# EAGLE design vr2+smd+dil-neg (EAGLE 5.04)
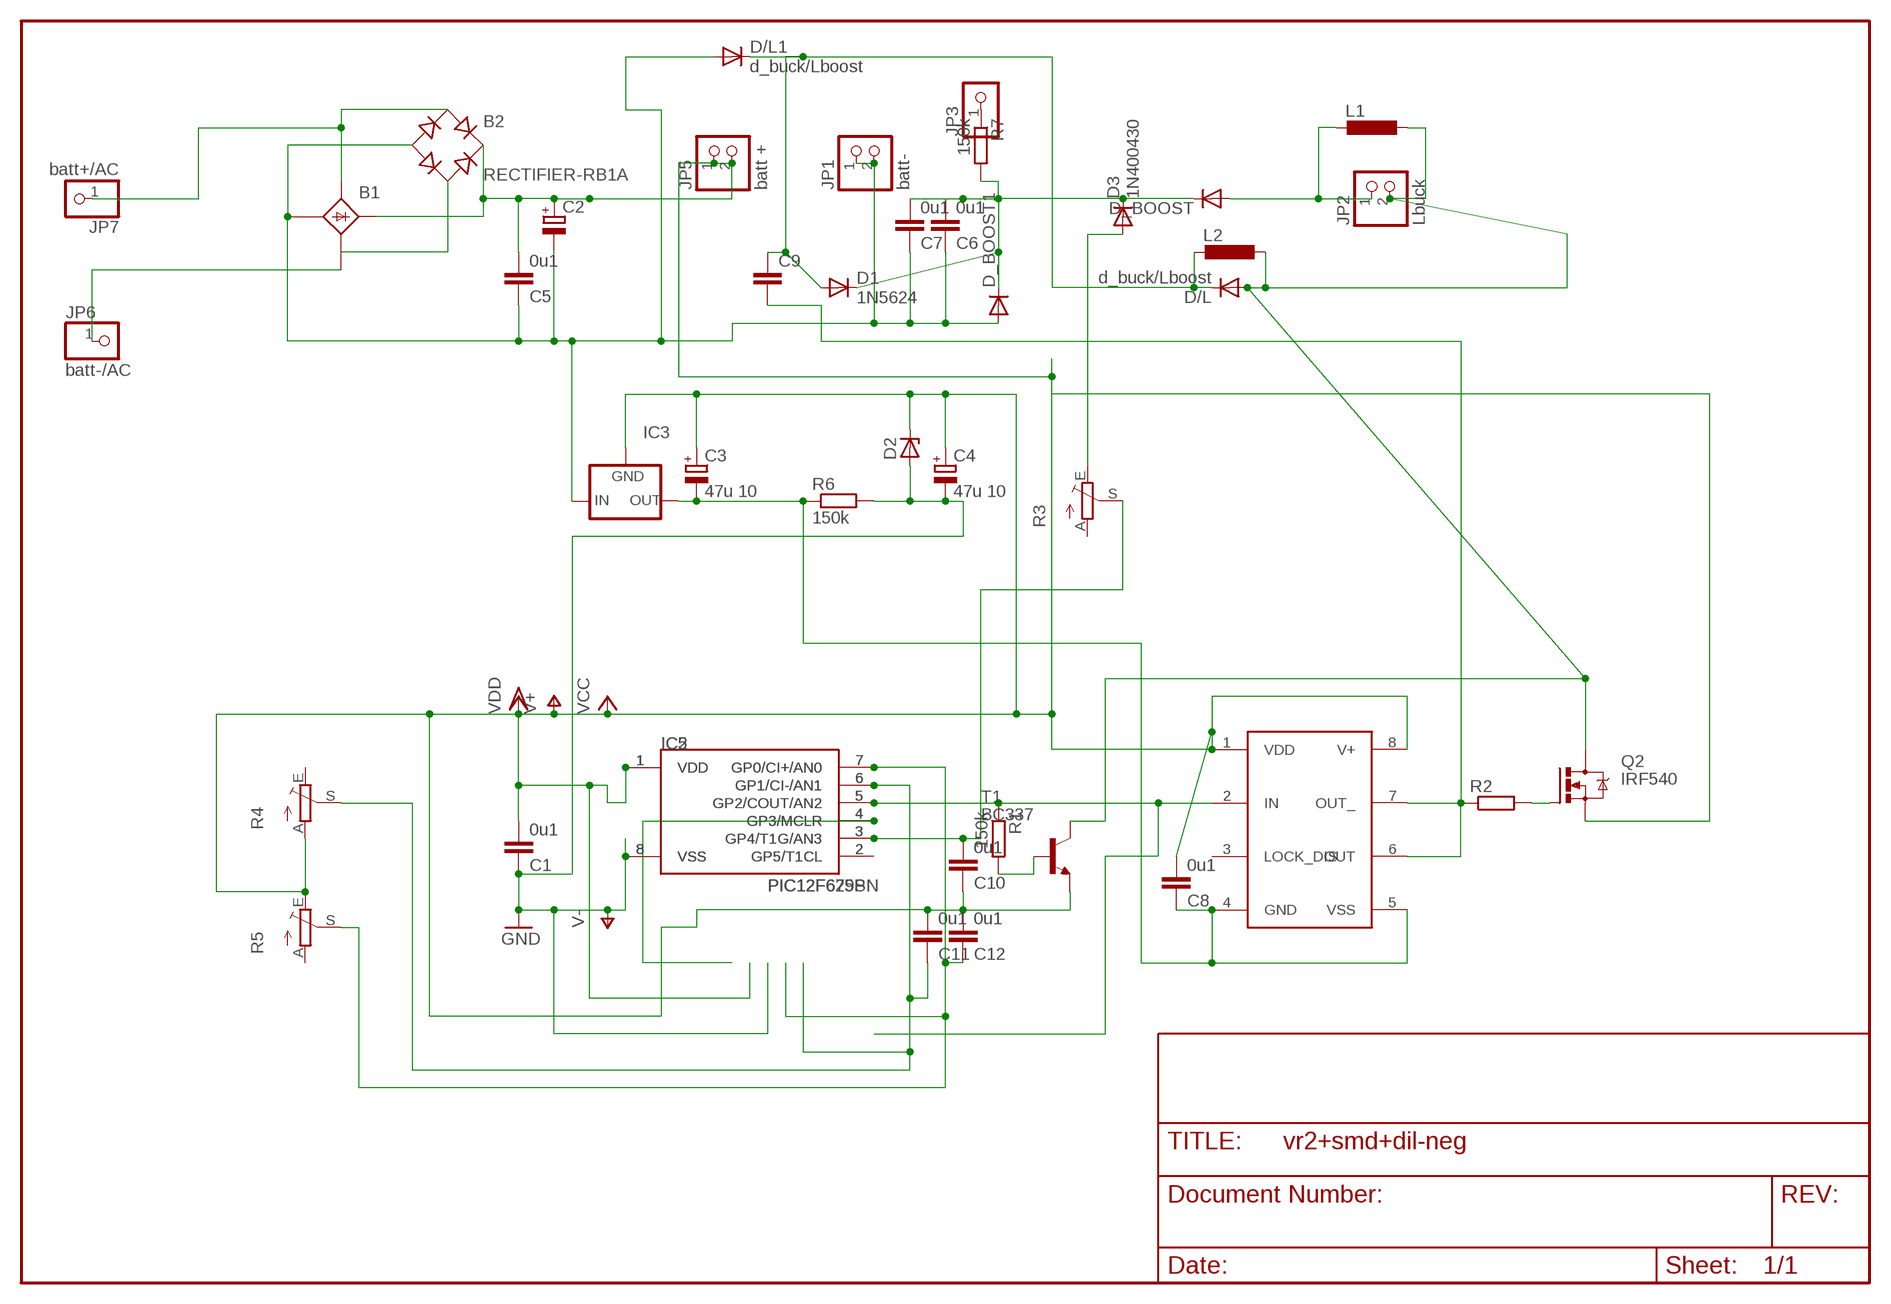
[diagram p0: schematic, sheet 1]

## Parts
B1  B25A-  [B25A-]
B2  RECTIFIER-RB1A  [RB1A]
C1  0u1  C-EUC1206  [C1206]
C2  CPOL-EUE7.5-18  [E7,5-18]
C3  47u 10  CPOL-EUE2,5-6E  [E2,5-6E]
C4  47u 10  CPOL-EUE2.5-6  [E2,5-6]
C5  0u1  C-EUC1206  [C1206]
C6  0u1  C-EUC1206  [C1206]
C7  0u1  C-EUC1206  [C1206]
C8  0u1  C-EUC1206  [C1206]
C9  C-EU050-024X044  [C050-024X044]
C10  0u1  C-EUC1206  [C1206]
C11  0u1  C-EUC1206  [C1206]
C12  0u1  C-EUC1206  [C1206]
D1  1N5624  [DO201-15]
D2  ZENER-DIODESMB  [SMB]
D3  1N400430  [DO41-30]
D/L  d_buck/Lboost  DIODE-C1702-05  [C1702-05]
D/L1  d_buck/Lboost  DIODE-DO201-15  [DO201-15]
D_BOOST  DIODE-DO201-15  [DO201-15]
D_BOOST1  DIODE-DO201-15  [DO201-15]
IC1  TC4432X  [SO-08]
IC2  PIC12F675SN  [SO-08]
IC3  79LXX  [79LXX]
IC5  PIC12F629P  [DIL8]
JP1  batt-  PINHD-1X2  [1X02]
JP2  Lbuck  PINHD-1X2  [1X02]
JP3  PINHD-1X1  [1X01]
JP5  batt +  PINHD-1X2  [1X02]
JP6  batt-/AC  PINHD-1X1  [1X01]
JP7  batt+/AC  PINHD-1X1  [1X01]
L1  DO3316P  [DO3316P]
L2  DO3316P  [DO3316P]
Q2  IRF540  [TO220BV]
R1  150k  R-EU_0617/17  [0617/17]
R2  R-EU_R1206  [R1206]
R3  TRIM_EU-CA6V  [CA6V]
R4  TRIM_EU-CA6V  [CA6V]
R5  TRIM_EU-CA6V  [CA6V]
R6  150k  R-EU_0204/7  [0204/7]
R7  150k  R-EU_0207/12  [0207/12]
T1  BC337  [TO92]

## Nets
LOAD: C6.2 C7.2 D1.C D3.C D_BOOST1.C D_BOOST.C R7.2
N$2: C9.1 D1.A D/L1.C D/L.C L2.1
N$3: B1.AC2-(AC2) JP6.1
N$5: D_BOOST.A JP2.1 L1.1
N$6: R1.2 T1.2(B)
N$7: C9.2 IC1.6(OUT) IC1.7(OUT_) R2.1
N$8: B1.AC1 B2.AC1 JP7.1
N$9: D/L.A JP2.2 L1.2 L2.2 Q2.D T1.3(C)
N$10: IC2.4(GP3/MCLR) IC5.4(GP3/MCLR)
N$11: B1.AC2 B2.AC2
N$12: C10.2 IC2.3(GP4/T1G/AN3) IC5.3(GP4/T1G/AN3) R3.S
N$13: C12.1 IC2.7(GP0/CI+/AN0) IC5.7(GP0/CI+/AN0) R5.S
N$14: IC1.2(IN) IC2.5(GP2/COUT/AN2) IC5.5(GP2/COUT/AN2) R1.1
N$15: C11.1 IC2.6(GP1/CI-/AN1) IC5.6(GP1/CI-/AN1) R4.S
N$16: D3.A R3.E
N$17: Q2.G R2.2
N$18: IC2.2(GP5/T1CL) IC5.2(GP5/T1CL)
N$19: JP3.1 R7.1
N$21: B1.-1(-) B2.- C2.- C5.1 C6.1 C7.1 D/L1.A D_BOOST1.A IC3.IN JP1.1 JP1.2
N$22: C3.- C8.1 IC1.4(GND) IC1.5(VSS) IC3.OUT R6.1
V+: B1.+ B2.+ C1.2 C2.+ C3.+ C4.+ C5.2 C8.2 C10.1 C11.2 C12.2 D2.C IC1.1(VDD) IC1.8(V+) IC2.1(VDD) IC3.GND IC5.1(VDD) JP5.1 JP5.2 Q2.S R4.A R5.E T1.1(E) ; supply symbol labelled VCC, VDD
V-: C1.1 C4.- D2.A IC2.8(VSS) IC5.8(VSS) R6.2 ; supply symbol labelled GND
Unconnected: B1.+1(+) B1.- B1.AC1-(AC1) IC1.3(LOCK_DIS) R3.A R4.E R5.A

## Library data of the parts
B1 = rectifier:B25A-: RECTIFIER 25-A bridge
B2 = rectifier:RECTIFIER-: Rectifier
C1 C5-C8 C10-C12 = rcl:C-EU: CAPACITOR, European symbol
C2-C4 = rcl:CPOL-EU: POLARIZED CAPACITOR, European symbol
C9 = rcl-2:C-EU: CAPACITOR, European symbol
D1 = diode-1:1N5624: DIODE
D2 = diode-1:ZENER-DIODE: Z-Diode
D3 = diode-1:1N4004: DIODE
D/L D/L1 D_BOOST D_BOOST1 = diode:DIODE-: DIODE
IC1 = microchip:TC4432
IC2 = microchip-3:PIC12F6*: uPC nW 1k Program Flash memory 2x Timer Comparator 10b A/D converter/ 4xIN
IC3 = v-reg:79LXX: VOLTAGE REGULATOR
IC5 = microchip-5:PIC12F6*: uPC nW 1k Program Flash memory 2x Timer Comparator 10b A/D converter/ 4xIN
JP1 JP2 JP5 = pinhead:PINHD-1X2: PIN HEADER
JP3 JP6 JP7 = pinhead:PINHD-1X1: PIN HEADER
L1 L2 = inductor-coilcraft:DO3316P: COILCRAFT
Q2 = transistor-power:IRF540: HEXFET Power MOSFET
R1 R6 R7 = rcl:R-EU_: RESISTOR, European symbol
R2 = rcl-2:R-EU_: RESISTOR, European symbol
R3-R5 = pot:TRIM_EU-: POTENTIOMETER
T1 = transistor-neu-to92:BC337: NPN TRANSISTOR

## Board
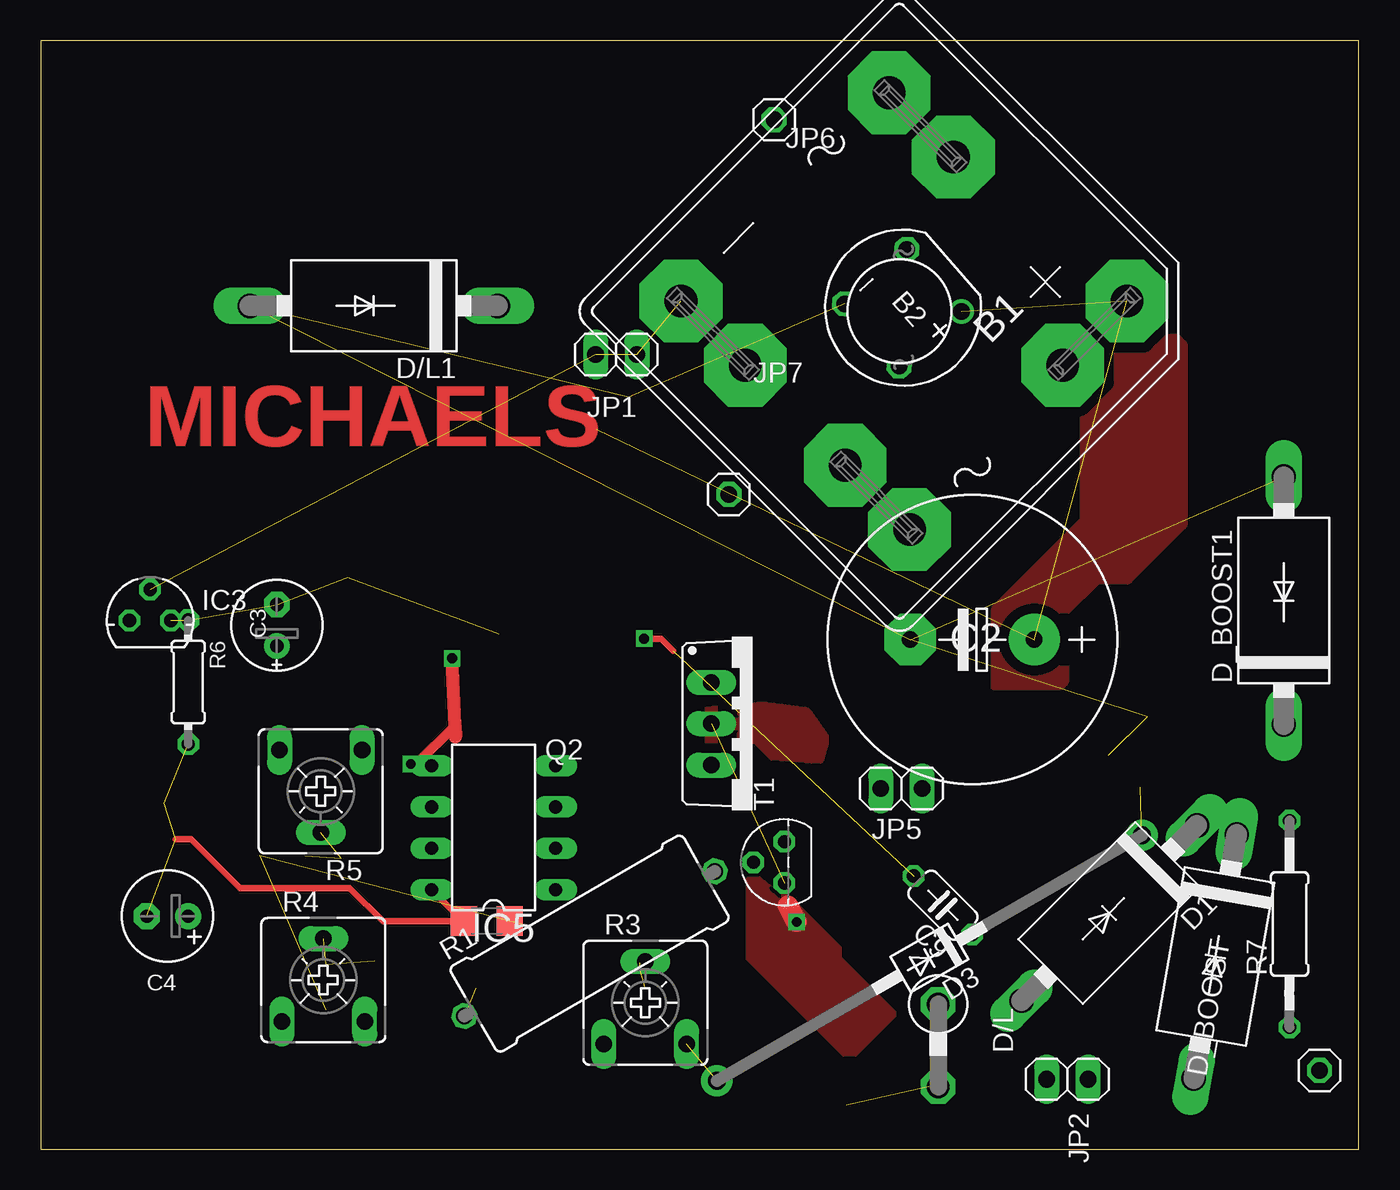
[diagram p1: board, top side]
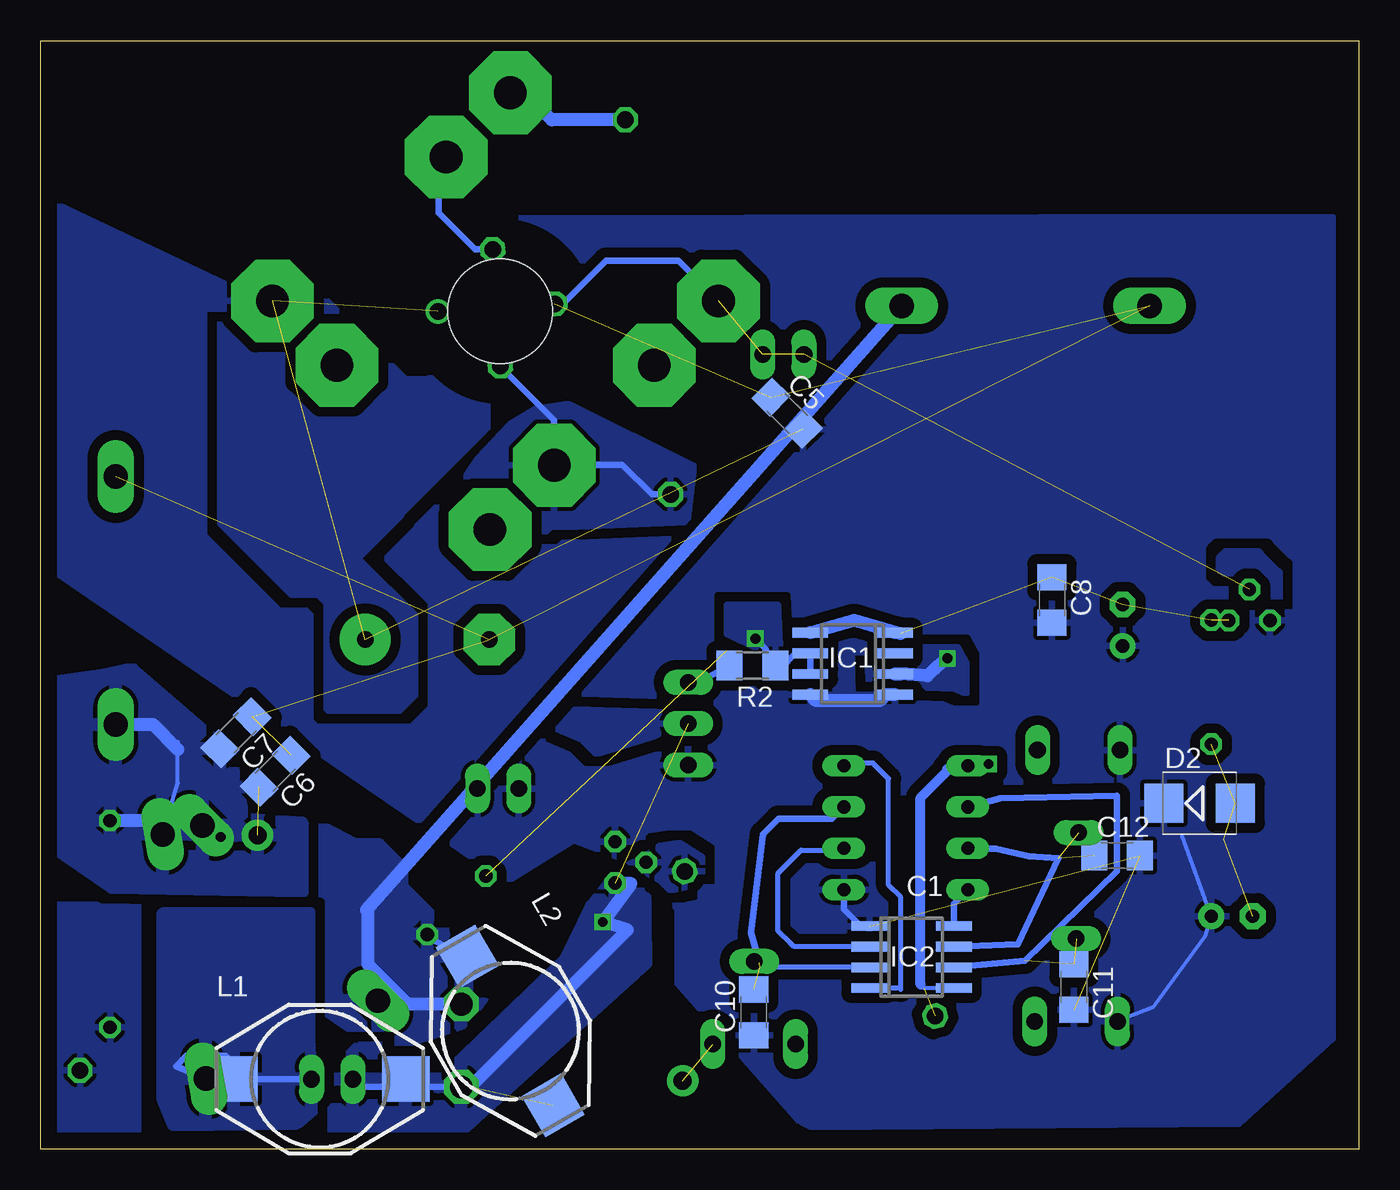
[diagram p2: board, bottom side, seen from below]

Size 81 x 68.09 mm. Coordinates in mm from the lower left corner, seen from the top.
Outline: 0,0 81,0 81,68.09 0,68.09 0,0
Copper layers (1*16): Top 0.035mm / dielectric 1.5mm / Bottom 0.035mm
Design rules "default": minimum track width 10mil, minimum drill 24mil, track to track 8mil, track to pad 8mil, pad to pad 8mil, via to via 8mil, smd to smd 8mil, copper to edge 40mil, drill to drill 8mil, minimum pad ring 10mil, minimum via ring 8mil, stop-mask expansion 4mil, vias tented up to drill 0mil, thermal gap 10mil

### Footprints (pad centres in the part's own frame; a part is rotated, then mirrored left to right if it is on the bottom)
B25A- = drill 2.007 pad 5.08 octagon: + -10.338,9.449; +1 -4.75,9.449; - 9.042,-4.343; -1 9.042,-9.931; AC1 9.042,4.343; AC1- 9.042,9.931; AC2 -9.042,-4.343; AC2- -9.042,-9.931 | hole 6.401: 0,0
RB1A = drill 1.016 round: + -2.54,2.54 | drill 1.016 octagon: - 2.54,-2.54; AC1 2.54,2.54; AC2 -2.54,-2.54
C1206 = smd 1.6 x 1.8: 1 -1.4,0; 2 1.4,0
E7,5-18 = drill 1.016 pad 3.15 round: + -3.81,0 | drill 1.016 pad 3.15 octagon: - 3.81,0
E2,5-6E = drill 0.813 pad 1.575 round: + -1.27,0 | drill 0.813 pad 1.575 octagon: - 1.27,0
E2,5-6 = drill 0.813 pad 1.6 round: + -1.27,0 | drill 0.813 pad 1.6 octagon: - 1.27,0
C050-024X044 = drill 0.813 octagon: 1 -2.54,0; 2 2.54,0
DO201-15 = drill 1.499 long: A 7.62,0; C -7.62,0
SMB = smd 2.4 x 2.4: A 2.2,0; C -2.2,0
DO41-30 = drill 1.118 pad 1.93 round: A 15.08,0; C -15.08,0
C1702-05 = drill 1.397 octagon: A 2.54,0; C -2.54,0
SO-08 = smd 0.6 x 2.2: 1 -1.905,-2.6; 2 -0.635,-2.6; 3 0.635,-2.6; 4 1.905,-2.6; 5 1.905,2.6; 6 0.635,2.6; 7 -0.635,2.6; 8 -1.905,2.6
79LXX = drill 0.813 octagon: GND -1.27,0; IN 0,1.905; OUT 1.27,0
DIL8 = drill 0.813 long: 1 -3.81,-3.81; 2 -1.27,-3.81; 3 1.27,-3.81; 4 3.81,-3.81; 5 3.81,3.81; 6 1.27,3.81; 7 -1.27,3.81; 8 -3.81,3.81
1X02 = drill 1.016 long: 1 -1.27,0; 2 1.27,0
1X01 = drill 1.016 octagon: 1 0,0
DO3316P = smd 2.92 x 2.79: 1 -5.28,0; 2 5.28,0
TO220BV = drill 1.016 long: D 0,-2.54; G -2.54,-2.54; S 2.54,-2.54
0617/17 = drill 1.016 octagon: 1 -8.89,0; 2 8.89,0
R1206 = smd 1.6 x 1.803: 1 -1.422,0; 2 1.422,0
CA6V = drill 1.016 long: A -2.54,-2.54; E 2.54,-2.54; S 0,2.54
0204/7 = drill 0.813 octagon: 1 -3.81,0; 2 3.81,0
0207/12 = drill 0.813 octagon: 1 -6.35,0; 2 6.35,0
TO92 = drill 0.813 octagon: 1 1.27,0; 2 0,1.905; 3 -1.27,0

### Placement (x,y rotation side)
B1  52.76,51.47 225 top
B2  52.99,51.69 221.3 top
C1  27.4,14.01 0 top
C2  57.25,31.31 180 top
C3  14.51,32.18 90 top
C4  7.79,14.31 180 top
C5  35.13,45.2 315 bottom
C6  66.59,23.21 225 bottom
C7  68.99,25.58 225 bottom
C8  18.86,33.73 270 bottom
C9  55.44,14.98 135 top
C10  37.18,8.41 90 bottom
C11  17.51,9.97 270 bottom
C12  14.84,18.03 0 bottom
D1  65.66,14.5 225 top
D2  9.79,21.25 0 bottom
D3  54.61,11.74 210 top
D/L  55.15,6.36 270 top
D/L1  20.47,51.8 180 top
D_BOOST  72.18,11.83 260 top
D_BOOST1  76.39,33.69 90 top
IC1  31.11,29.82 90 bottom
IC2  27.48,11.8 270 bottom
IC3  6.73,32.47 0 top
IC5  27.84,19.75 90 top
JP1  35.37,48.82 180 top
JP2  63.09,4.29 180 top
JP3  78.58,4.84 0 top
JP5  52.89,22.15 180 top
JP6  45.07,63.23 0 top
JP7  42.29,40.22 0 top
L1  63.85,4.31 0 bottom
L2  52.14,7.26 300 bottom
Q2  43.75,26.14 270 top
R1  33.73,12.62 30 top
R2  37.26,29.71 180 bottom
R3  37.16,8.99 0 top
R4  17.37,10.39 0 top
R5  17.21,21.98 180 top
R6  9.06,28.69 270 top
R7  76.74,13.83 90 top
T1  45.7,17.61 90 top

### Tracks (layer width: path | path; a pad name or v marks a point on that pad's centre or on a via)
LOAD  (via drill 0.6)  (1 unrouted)
  Bottom 0.254: 72.58,25.02 72.58,24.55 72.58,22.48 D_BOOST.C
  Bottom 0.406: 72.7,20.46 72.83,20.59 | 72.7,20.46 D_BOOST.C | v69.94,19.18 71.29,19.05 72.7,20.46
  Bottom 0.813: D_BOOST1.C 74.1,26.07 72.58,24.55 | D_BOOST.C 72.6,20.34 72.58,20.32 72.72,20.18 R7.2
  pour Bottom (isolate 0.61, rank 2): 68.51,20.29 64.94,20.04 64.93,15.84 76.62,16.07 81.04,19.1 81.04,28.59 77.09,29.13 75.4,29.51 69.44,24.38
N$1
  pour Bottom (isolate 0.61): 5.6,33.03 5.04,33.59 5.04,35.32 6.23,36.51 8.12,36.51 8.44,36.2 8.44,35.8
  pour Bottom (isolate 0.61, rank 2): 53.54,49 53.54,44.32 58.86,39 58.86,38.9 61.71,36.06 61.24,36.06 58,32.82 58,27.88 58.95,26.92 63.33,26.92 63.42,27.01 63.42,33.5 63.98,34.06 65.6,34.06 69.97,38.43 69.97,52.18 66.8,55.36 66.66,55.36 58.58,47.28 57.22,47.28 55.85,48.65 55.85,48.78 55.85,49.06 55.44,49.47
  pour Top (isolate 0.61): 69.62,49.81 70.08,49.35 70.08,38.39 66.76,35.08 64.83,35.08 62.79,33.03 62.79,28.79 62.56,28.56 58.68,28.56 58.8,28.68 58.8,33.13 64.26,38.6 64.26,48.09
N$2
  Bottom 0.406: L2.1 57.24,13.03 C9.1
  Bottom 0.813: D/L.C 58.42,8.9 60.88,11.37 60.88,14.57 60.99,14.68 D/L1.C
  pour Bottom (isolate 0.61, rank 3): 53.36,11.19 53.63,9.65 55,7.75 59.95,6.12 64.45,9.22 64.32,20.07 61.73,18.72 60.22,18.72 58.82,17.32 58.82,16.14 54.73,12.05
N$3
  Bottom 0.813: JP6.1 49.6,63.23 51.95,65.58 51.95,64.49 51.67,64.21 51.69,64.21 52.13,64.66 B1.AC2-
N$5
  Bottom 0.406: JP2.1 68.21,4.29 69.64,5.73 72.04,5.73 72.67,5.11 D_BOOST.A
  pour Bottom (isolate 0.61): 64.31,4.23 64.5,6.5 64.5,14.5 73.5,14.45 73.5,3.07 72.84,1.51 65.27,1.6 64.27,2.45
N$6
  pour Bottom (isolate 0.61): 44.8,17.54 43.14,18.44 42.96,18.64 41.72,18.83 40.36,17.96 40.36,16.78 41.39,16.09 42.34,15.88 42.94,16.47
N$7  (via drill 0.6)  (1 unrouted)
  Top 0.406: v37.08,31.36 38.13,31.36 38.87,30.62
  Bottom 0.406: 33.87,29.18 33.92,29.13 | IC1.7 33.87,29.18 | 33.87,29.18 33.71,29.34 IC1.6 34.6,30.45 35.45,29.6 35.98,29.68 R2.1 36.03,29.83 36.47,30.75 v37.08,31.36
  pour Bottom: 36.37,29.49 35.58,30.92 35.68,33.43 38.83,33.43 38.83,31.64 36.37,30.45
N$8
  Bottom 0.406: JP7.1 43.44,40.22 45.27,42.05 49.48,42.05 | 49.48,42.05 50.3,42.05 | 49.48,42.05 B1.AC1 49.44,44.78 B2.AC1
  pour Bottom (isolate 0.61, rank 2): 50.61,45.49 48.56,45.8 40.84,41.99 41.26,38.52 48.03,38.24 49.63,38.24 52.38,35.64 54.98,35.2 56.88,37.11 56.11,39.52 54.12,42.46 52.16,44.55
N$9  (via drill 0.6)  (2 unrouted)
  Top 1.27: v46.45,13.96 45.91,14.96
  Bottom 0.406: 61.98,4.29 61.98,4.46 | 61.98,4.29 JP2.2 | D/L.A 61.98,3.82 61.98,4.29
  Bottom 0.813: D/L.A 54.58,3.82 44.94,13.46 v46.45,13.96 44.73,16.31 T1.3
  pour Bottom (isolate 0.813): 42.08,26.85 46.47,26.96 52.55,27.19 47.8,25.17 46.87,24.24 43.29,25.37 42.44,25.79
  pour Bottom (isolate 0.61, rank 2): 43.86,16.68 46.05,16.33 47.15,14.92 48.73,11.7 56.38,4.33 58.16,4.33 60.02,6.18 61.53,6.18 62.39,5.32 65.74,0.47 65.21,-0.06 56.51,-0.06 43.8,11.46
  pour Top: 45.3,15.61 45.79,15.61 49.03,12.37 49.03,11.76 52.44,8.36 52.44,8.24 50.07,5.88 49.36,5.88 43.53,11.71 43.53,16.59 43.76,16.81
  pour Top (isolate 0.61): 40.37,26.54 40.6,26.77 44.36,27.11 46.97,26.77 48.12,25.17 47.77,24.03 45.04,24.26 44.01,25.29 40.26,25.29
N$10
  Bottom 0.305: IC2.4 28.25,9.89 28.15,9.79 28.15,15.47 28.9,16.22 28.9,22.76 29.85,23.71 31.49,23.71 IC5.4
N$11
  Bottom 0.406: B2.AC2 54.32,55.27 56.56,57.52 56.56,60.46 B1.AC2
N$12  (2 unrouted)
  Bottom 0.305: IC2.3 36.79,11.16 R3.S
  Bottom 0.406: 36.84,11.46 37.35,13.28 36.61,19.33 35.66,20.28 32.38,20.28 IC5.3
N$13  (2 unrouted)
  Bottom 0.406: IC2.7 20.94,12.59 18.45,17.88 20.27,17.98 22.31,18.47 24.01,18.47 IC5.7
N$14  (via drill 0.6)  (1 unrouted)
  Top 0.61: v22.74,23.66 23.11,23.66 25.46,26
  Top 0.813: 25.49,25.31 25.46,26 v25.28,30.15
  Bottom 0.254: IC2.5 26.72,9.89 26.93,10.11 | 25.16,23.36 24.23,23.36 IC5.5
  Bottom 0.61: 26.93,10.11 26.93,21.58 25.16,23.36 25.28,23.36 v22.74,23.66
  Bottom 0.813: v25.28,30.15 26.04,29.54 26.51,29.07 28.14,29.2 28.15,29.18 IC1.2
  pour Bottom (isolate 0.61): 26.55,28.33 24.86,28.27 24.11,27.97 24.11,29.87 24.65,30.84 30.24,30.85 30.13,28.84 26.86,28.65
N$15  (2 unrouted)
  Bottom 0.406: IC2.6 20.52,11.58 14.86,17.06 14.88,21.72 22.03,21.55 24.01,21.01 IC5.6
N$16  (1 unrouted)
N$17
  Bottom 0.406: Q2.G 41.15,28.68 40.95,28.49 R2.2
N$18
  Bottom 0.305: IC2.2 34.71,12.43 34.88,12.61 34.9,12.61 35.68,13.4 35.68,16.95 34.27,18.36 31.76,18.36 IC5.2
N$19
  pour Bottom (isolate 0.61, rank 3): 75,1.13 81.01,1.22 81.24,3.64 81.24,11.06 80,15 78,15 75,15.05
N$21  (9 unrouted)
  Bottom 0.406: B2.- 48.9,51.92 46.26,54.56 41.8,54.56 B1.-1
N$22  (4 unrouted)
  Bottom 0.813: IC1.4 31.01,32.49 | 31.01,32.49 IC1.5 | 31.01,32.49 28.16,31.67
V+  (6 unrouted)
  Bottom 0.254: R4.A 12.63,8.72 9.45,13.08 C4.+ 10.86,19.21
  Bottom 0.406: IC2.1 30.6,13.7 31.64,14.74 IC5.1
  Bottom 0.813: IC1.1 29.08,27.91 29.43,27.56 33.37,27.56 33.71,27.9 IC1.8
  pour Bottom (isolate 0.61, rank 4): 1.6,57.29 1.6,6.79 7.34,1.55 33.66,1.36 34.45,1.78 41.87,10.15 41.87,14.69 43.66,17.21 48.23,18.97 52.35,16.43 80.77,35.9 80.77,44.59 81.1,58.56 48.45,43.12 55.83,57.18
V-  (3 unrouted)
  Top 0.406: 8.29,19.05 9.24,19.05 12.25,16.04 19,16.04 21.03,14.01 C1.1 25.96,14.01 IC5.8
  Bottom 0.406: IC2.8 24.88,15.08 IC5.8 23.98,15.98

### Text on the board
Top: MICHAELS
